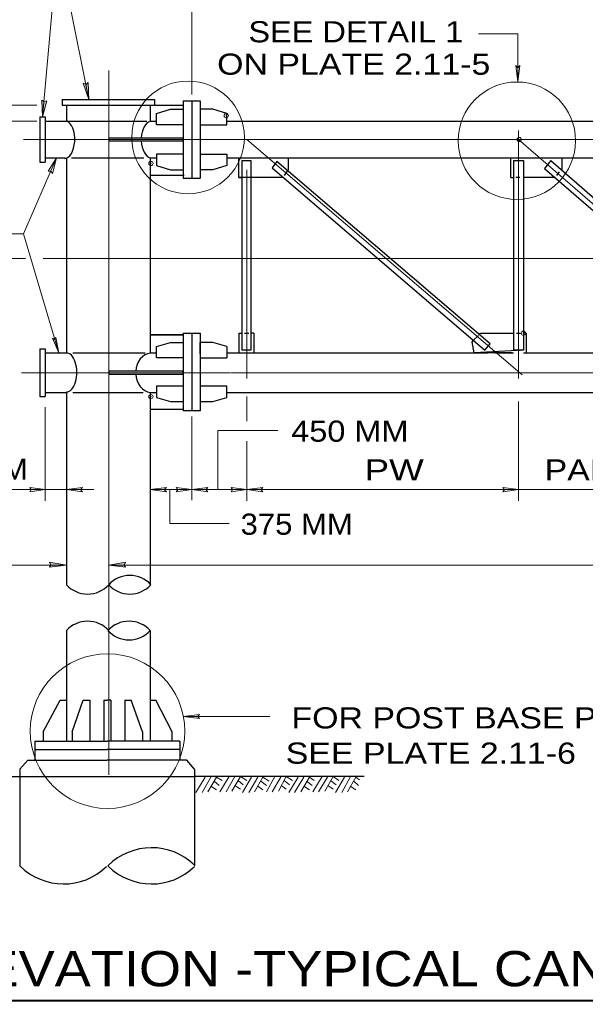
# Model space of a CAD drawing. Extents: x 312601.858 to 312602.699, y 144420.109 to 144420.704.
# Drawn here: x 312601.9927 to 312602.0731, y 144420.4937 to 144420.6329 of the extents above; entities that cross this region are included whole.
import ezdxf
from ezdxf.enums import TextEntityAlignment as Align

# ---------------------------------------------------------------- set-up
doc = ezdxf.new("R2010")
doc.units = 0
doc.header["$LTSCALE"] = 0.0012
doc.header["$PDMODE"] = 32
doc.header["$PDSIZE"] = 0.0006
for name, pattern in [('DOT_DASHED', [7.7, 5, -1.2, 0.3, -1.2]), ('LONG_DASHED', [7.5, 6, -1.5]), ('MEDIUM_DASHED', [4.5, 3, -1.5])]:
    doc.linetypes.add(name, pattern=pattern)
for name, color, linetype, lineweight in [('1', 7, 'Continuous', 13), ('2', 7, 'Continuous', 25), ('39', 7, 'Continuous', 13)]:
    doc.layers.add(name, color=color, linetype=linetype, lineweight=lineweight)

msp = doc.modelspace()

# ---------------------------------------------------------------- hatches: boundary and pattern name
at = {"layer": '39'}
for points in [[(312602.0022, 144420.6237), (312602.0025, 144420.624), (312602.0026, 144420.6216), (312602.0018, 144420.6239)], [(312601.9962, 144420.6213), (312601.9966, 144420.6214), (312601.996, 144420.6191), (312601.9959, 144420.6215)], [(312601.9972, 144420.5555), (312601.997, 144420.5559), (312601.9994, 144420.5555), (312601.997, 144420.5552)], [(312602.0076, 144420.5555), (312602.0078, 144420.5552), (312602.0054, 144420.5555), (312602.0078, 144420.5559)]]:
    msp.add_hatch(color=256, dxfattribs=at).paths.add_polyline_path(points)

# ---------------------------------------------------------------- linework, layer by layer
at = {"layer": '1'}
for p, q in [((312602.0026, 144420.6216), (312601.9982, 144420.6435)), ((312602.0172, 144420.6414), (312602.0172, 144420.6223)), ((312602.0579, 144420.6309), (312602.0635, 144420.6309)), ((312602.0635, 144420.6309), (312602.0635, 144420.6241)), ((312601.9878, 144420.6208), (312601.9952, 144420.6208)), ((312601.9879, 144420.6185), (312601.9952, 144420.6185)), ((312601.9843, 144420.6025), (312601.9933, 144420.6025)), ((312601.9818, 144420.599), (312601.9936, 144420.599)), ((312602.025, 144420.5759), (312602.025, 144420.5794)), ((312602.0636, 144420.5646), (312602.0636, 144420.5787)), ((312601.9964, 144420.5779), (312601.9964, 144420.5646)), ((312602.0172, 144420.5766), (312602.0172, 144420.5647)), ((312602.0209, 144420.5746), (312602.0294, 144420.5746)), ((312602.025, 144420.5646), (312602.025, 144420.5731)), ((312601.9994, 144420.5662), (312602.0033, 144420.5662)), ((312602.0113, 144420.5662), (312602.0168, 144420.5662)), ((312602.0168, 144420.5662), (312602.025, 144420.5662)), ((312602.025, 144420.5662), (312602.0636, 144420.5662)), ((312602.0636, 144420.5662), (312602.1312, 144420.5662)), ((312602.0141, 144420.5614), (312602.0225, 144420.5614)), ((312601.9823, 144420.5555), (312601.9994, 144420.5555)), ((312602.0054, 144420.5555), (312602.1817, 144420.5555)), ((312601.9994, 144420.5363), (312601.9987, 144420.5363)), ((312602.016, 144420.534), (312602.0283, 144420.534)), ((312602.0178, 144420.5232), (312602.0191, 144420.5254)), ((312602.0187, 144420.5232), (312602.0199, 144420.5254)), ((312602.0195, 144420.5233), (312602.0207, 144420.5254)), ((312602.0207, 144420.5254), (312602.0215, 144420.5249)), ((312602.0212, 144420.5233), (312602.0225, 144420.5255)), ((312602.0221, 144420.5233), (312602.0233, 144420.5255)), ((312602.0229, 144420.5234), (312602.0241, 144420.5255)), ((312602.0241, 144420.5255), (312602.025, 144420.5249)), ((312602.0244, 144420.5232), (312602.0257, 144420.5254)), ((312602.0253, 144420.5232), (312602.0266, 144420.5254)), ((312602.0261, 144420.5233), (312602.0273, 144420.5254)), ((312602.0273, 144420.5254), (312602.0282, 144420.5248)), ((312602.0278, 144420.5233), (312602.029, 144420.5255)), ((312602.0286, 144420.5233), (312602.0299, 144420.5255)), ((312602.0295, 144420.5234), (312602.0306, 144420.5255)), ((312602.0306, 144420.5255), (312602.0315, 144420.5249)), ((312602.031, 144420.5232), (312602.0323, 144420.5254)), ((312602.0318, 144420.5232), (312602.0331, 144420.5254)), ((312602.0327, 144420.5233), (312602.0339, 144420.5254)), ((312602.0339, 144420.5254), (312602.0346, 144420.5249)), ((312602.0344, 144420.5233), (312602.0357, 144420.5255)), ((312602.0352, 144420.5233), (312602.0365, 144420.5255)), ((312602.0361, 144420.5234), (312602.0373, 144420.5255)), ((312602.0373, 144420.5255), (312602.0381, 144420.5249)), ((312602.0376, 144420.5232), (312602.0389, 144420.5254)), ((312602.0385, 144420.5232), (312602.0397, 144420.5254)), ((312602.0393, 144420.5233), (312602.0405, 144420.5254)), ((312602.0405, 144420.5254), (312602.041, 144420.525)), ((312602.0199, 144420.5241), (312602.0207, 144420.5236)), ((312602.0204, 144420.5248), (312602.0211, 144420.5242)), ((312602.0233, 144420.5242), (312602.0241, 144420.5237)), ((312602.0238, 144420.5249), (312602.0245, 144420.5243)), ((312602.0266, 144420.5241), (312602.0273, 144420.5236)), ((312602.027, 144420.5248), (312602.0278, 144420.5242)), ((312602.0299, 144420.5242), (312602.0306, 144420.5237)), ((312602.0303, 144420.5249), (312602.0311, 144420.5243)), ((312602.0331, 144420.5241), (312602.0339, 144420.5236)), ((312602.0335, 144420.5248), (312602.0343, 144420.5242)), ((312602.0365, 144420.5242), (312602.0373, 144420.5237)), ((312602.0369, 144420.5249), (312602.0377, 144420.5243)), ((312602.0397, 144420.5241), (312602.0405, 144420.5236)), ((312602.0402, 144420.5248), (312602.0409, 144420.5242))]:
    msp.add_line(p, q, dxfattribs=at)
at = {"layer": '1', "lineweight": 25}
for p, q in [((312601.9988, 144420.6216), (312602.0119, 144420.6216)), ((312601.9988, 144420.6216), (312601.9988, 144420.6208)), ((312602.0119, 144420.6216), (312602.0119, 144420.6208)), ((312601.9988, 144420.6208), (312602.0119, 144420.6208)), ((312601.9994, 144420.6208), (312601.9994, 144420.6185)), ((312602.0113, 144420.6208), (312602.0113, 144420.6185)), ((312601.9956, 144420.6191), (312601.9956, 144420.6127)), ((312601.9956, 144420.6191), (312601.9964, 144420.6191)), ((312601.9964, 144420.6191), (312601.9964, 144420.6127)), ((312601.9964, 144420.6185), (312601.9994, 144420.6185)), ((312602.0113, 144420.6185), (312602.0122, 144420.6185)), ((312602.0222, 144420.6185), (312602.1817, 144420.6185)), ((312601.9964, 144420.6133), (312601.9992, 144420.6133)), ((312601.9994, 144420.6133), (312601.9994, 144420.5856)), ((312602.0113, 144420.6133), (312602.0122, 144420.6133)), ((312602.0113, 144420.6133), (312602.0113, 144420.5856)), ((312602.0222, 144420.6133), (312602.0255, 144420.6133)), ((312602.0239, 144420.6105), (312602.0239, 144420.6133)), ((312602.0239, 144420.6105), (312602.0239, 144420.6133)), ((312602.0239, 144420.6105), (312602.0239, 144420.6133)), ((312602.0243, 144420.6129), (312602.0243, 144420.586)), ((312602.0243, 144420.6129), (312602.0256, 144420.6129)), ((312602.0255, 144420.6133), (312602.0293, 144420.6133)), ((312602.0256, 144420.6129), (312602.0256, 144420.586)), ((312602.0293, 144420.6128), (312602.0286, 144420.6119)), ((312602.029, 144420.6133), (312602.063, 144420.6133)), ((312602.0596, 144420.5869), (312602.0293, 144420.6128)), ((312602.0629, 144420.6129), (312602.0629, 144420.586)), ((312602.0629, 144420.6129), (312602.0643, 144420.6129)), ((312602.0641, 144420.6133), (312602.0679, 144420.6133)), ((312602.0682, 144420.6129), (312602.0673, 144420.6118)), ((312602.0677, 144420.6133), (312602.1012, 144420.6133)), ((312602.0682, 144420.6129), (312602.0981, 144420.5869)), ((312602.0698, 144420.6117), (312602.0698, 144420.6133)), ((312601.9956, 144420.6127), (312601.9964, 144420.6127)), ((312602.0286, 144420.6119), (312602.0588, 144420.586)), ((312602.0673, 144420.6118), (312602.0972, 144420.5859)), ((312602.0698, 144420.6117), (312602.0697, 144420.6116)), ((312602.0239, 144420.6105), (312602.0243, 144420.6105)), ((312602.0239, 144420.6105), (312602.0243, 144420.6105)), ((312602.0239, 144420.6105), (312602.0243, 144420.6105)), ((312602.03, 144420.6105), (312602.0256, 144420.6105)), ((312602.03, 144420.6105), (312602.0256, 144420.6105)), ((312602.0625, 144420.6105), (312602.0629, 144420.6105)), ((312602.0638, 144420.6105), (312602.0632, 144420.6105)), ((312602.0694, 144420.6113), (312602.069, 144420.6108)), ((312602.0239, 144420.5884), (312602.0243, 144420.5884)), ((312602.0239, 144420.5884), (312602.0239, 144420.5856)), ((312602.0247, 144420.5884), (312602.0253, 144420.5884)), ((312602.026, 144420.5884), (312602.0256, 144420.5884)), ((312602.026, 144420.5884), (312602.026, 144420.5856)), ((312602.058, 144420.5882), (312602.0582, 144420.5884)), ((312602.0582, 144420.5884), (312602.0629, 144420.5884)), ((312602.0582, 144420.5884), (312602.0626, 144420.5884)), ((312602.0582, 144420.5884), (312602.0626, 144420.5884)), ((312602.0582, 144420.5884), (312602.0626, 144420.5884)), ((312602.0633, 144420.5884), (312602.0639, 144420.5884)), ((312602.0647, 144420.5884), (312602.0643, 144420.5884)), ((312602.0647, 144420.5884), (312602.0647, 144420.5856)), ((312602.0184, 144420.5855), (312602.0184, 144420.5871)), ((312602.0222, 144420.5865), (312602.0222, 144420.5849)), ((312602.0588, 144420.586), (312602.0596, 144420.5869)), ((312601.9956, 144420.5862), (312601.9956, 144420.5794)), ((312601.9956, 144420.5862), (312601.9964, 144420.5862)), ((312601.9964, 144420.5862), (312601.9964, 144420.5794)), ((312601.9964, 144420.5856), (312601.9994, 144420.5856)), ((312602.0113, 144420.5856), (312602.0122, 144420.5856)), ((312602.0222, 144420.5856), (312602.0226, 144420.5856)), ((312602.0223, 144420.5856), (312602.0256, 144420.5856)), ((312602.0233, 144420.5856), (312602.0234, 144420.5856)), ((312602.0256, 144420.586), (312602.0243, 144420.586)), ((312602.0256, 144420.5856), (312602.0592, 144420.5856)), ((312602.0627, 144420.5856), (312602.0589, 144420.5856)), ((312602.0603, 144420.5856), (312602.0624, 144420.5856)), ((312602.0604, 144420.5856), (312602.0627, 144420.5856)), ((312602.0606, 144420.5856), (312602.0627, 144420.5856)), ((312602.0625, 144420.5856), (312602.0606, 144420.5856)), ((312602.0608, 144420.5856), (312602.0629, 144420.5856)), ((312602.0643, 144420.586), (312602.0629, 144420.586)), ((312602.0643, 144420.5856), (312602.0976, 144420.5856)), ((312601.9956, 144420.5794), (312601.9964, 144420.5794)), ((312601.9964, 144420.58), (312601.9994, 144420.58)), ((312601.9994, 144420.58), (312601.9994, 144420.5527)), ((312602.0113, 144420.58), (312602.0113, 144420.5527)), ((312602.0113, 144420.58), (312602.0122, 144420.58)), ((312602.0222, 144420.58), (312602.0226, 144420.58)), ((312602.0222, 144420.58), (312602.1817, 144420.58)), ((312602.0233, 144420.58), (312602.0234, 144420.58)), ((312602.0184, 144420.5774), (312602.016, 144420.5774)), ((312601.9994, 144420.5462), (312601.9994, 144420.5305)), ((312602.0113, 144420.5462), (312602.0113, 144420.5305)), ((312601.9961, 144420.5318), (312601.9985, 144420.5363)), ((312601.9985, 144420.5363), (312601.9994, 144420.5363)), ((312602.0018, 144420.5363), (312602.0027, 144420.5363)), ((312602.0027, 144420.5363), (312602.0027, 144420.5305)), ((312602.0047, 144420.5363), (312602.0047, 144420.5305)), ((312602.0047, 144420.5363), (312602.0052, 144420.5363)), ((312602.0057, 144420.5363), (312602.0052, 144420.5363)), ((312602.0057, 144420.5363), (312602.0057, 144420.5305)), ((312602.0077, 144420.5363), (312602.0086, 144420.5363)), ((312602.0077, 144420.5363), (312602.0077, 144420.5305)), ((312602.0113, 144420.5363), (312602.0121, 144420.5363)), ((312602.0144, 144420.5318), (312602.0121, 144420.5363)), ((312601.9961, 144420.5318), (312601.9961, 144420.5305)), ((312602.0002, 144420.5318), (312602.0002, 144420.5305)), ((312602.0102, 144420.5318), (312602.0102, 144420.5305)), ((312602.0144, 144420.5306), (312602.0144, 144420.5318)), ((312601.9949, 144420.5305), (312602.0052, 144420.5305)), ((312601.9949, 144420.5305), (312601.9949, 144420.5279)), ((312601.9949, 144420.5293), (312602.0052, 144420.5293)), ((312602.0155, 144420.5305), (312602.0052, 144420.5305)), ((312602.0155, 144420.5293), (312602.0052, 144420.5293)), ((312602.0155, 144420.5305), (312602.0155, 144420.5279)), ((312601.9928, 144420.5265), (312601.9939, 144420.5278)), ((312601.9939, 144420.5278), (312602.0052, 144420.5278)), ((312602.0165, 144420.5278), (312602.0052, 144420.5278)), ((312602.0176, 144420.5265), (312602.0165, 144420.5278)), ((312601.9688, 144420.5255), (312602.0175, 144420.5255)), ((312602.0417, 144420.5255), (312602.0176, 144420.5255))]:
    msp.add_line(p, q, dxfattribs=at)
at = {"layer": '1', "linetype": 'MEDIUM_DASHED', "lineweight": 25}
for p, q in [((312601.9997, 144420.6185), (312602.0108, 144420.6185)), ((312602.0001, 144420.6133), (312602.0104, 144420.6133)), ((312602.0003, 144420.5856), (312602.0106, 144420.5856)), ((312602.0003, 144420.58), (312602.0103, 144420.58))]:
    msp.add_line(p, q, dxfattribs=at)
at = {"layer": '1', "linetype": 'DOT_DASHED'}
for p, q in [((312602.0636, 144420.582), (312602.0636, 144420.6172)), ((312601.9933, 144420.6159), (312602.1862, 144420.6159)), ((312602.025, 144420.6159), (312602.0641, 144420.5825)), ((312602.0636, 144420.6159), (312602.1019, 144420.5828)), ((312602.0639, 144420.6159), (312602.0637, 144420.6159)), ((312602.025, 144420.582), (312602.025, 144420.6116)), ((312601.9961, 144420.599), (312602.181, 144420.599)), ((312601.993, 144420.5828), (312602.0117, 144420.5828)), ((312602.012, 144420.5828), (312602.0226, 144420.5828)), ((312602.0222, 144420.5828), (312602.0226, 144420.5828)), ((312602.0233, 144420.5828), (312602.0234, 144420.5828))]:
    msp.add_line(p, q, dxfattribs=at)
at = {"layer": '1', "linetype": 'LONG_DASHED', "lineweight": 25}
for p, q in [((312601.9928, 144420.5265), (312601.9928, 144420.5128)), ((312602.0176, 144420.5265), (312602.0176, 144420.5128))]:
    msp.add_line(p, q, dxfattribs=at)
at = {"layer": '1', "lineweight": 40}
msp.add_line((312601.9778, 144420.4937), (312602.169, 144420.4937), dxfattribs=at)
at = {"layer": '1'}
for points in [[(312602.0638, 144420.6264), (312602.0635, 144420.6241), (312602.0632, 144420.6264), (312602.0635, 144420.6261)], [(312601.9968, 144420.6114), (312601.998, 144420.6133), (312601.9974, 144420.6111), (312601.9972, 144420.6114)], [(312601.9979, 144420.5878), (312601.9983, 144420.5856), (312601.9974, 144420.5877), (312601.9977, 144420.5875)], [(312601.9942, 144420.5665), (312601.9964, 144420.5662), (312601.9942, 144420.5659), (312601.9944, 144420.5662)], [(312602.0017, 144420.5659), (312601.9994, 144420.5662), (312602.0017, 144420.5665), (312602.0014, 144420.5662)], [(312602.0136, 144420.5659), (312602.0113, 144420.5662), (312602.0136, 144420.5665), (312602.0133, 144420.5662)], [(312602.015, 144420.5665), (312602.0172, 144420.5662), (312602.015, 144420.5659), (312602.0152, 144420.5662)], [(312602.0195, 144420.5659), (312602.0172, 144420.5662), (312602.0195, 144420.5665), (312602.0192, 144420.5662)], [(312602.0228, 144420.5665), (312602.025, 144420.5662), (312602.0228, 144420.5659), (312602.023, 144420.5662)], [(312602.0273, 144420.5659), (312602.025, 144420.5662), (312602.0273, 144420.5665), (312602.027, 144420.5662)], [(312602.0614, 144420.5665), (312602.0636, 144420.5662), (312602.0614, 144420.5659), (312602.0616, 144420.5662)], [(312602.0183, 144420.5337), (312602.016, 144420.534), (312602.0183, 144420.5343), (312602.018, 144420.534)]]:
    msp.add_lwpolyline(points, close=True, dxfattribs=at)
for points in [[(312601.9983, 144420.5856), (312601.9933, 144420.6025), (312601.998, 144420.6133)], [(312601.9778, 144420.5662), (312601.9964, 144420.5662), (312601.9994, 144420.5662)]]:
    msp.add_lwpolyline(points, dxfattribs=at)
at = {"layer": '1', "lineweight": 25}
for points in [[(312602.03, 144420.6105), (312602.0256, 144420.6105), (312602.0246, 144420.6105), (312602.0239, 144420.6105), (312602.0239, 144420.6133), (312602.0309, 144420.6133), (312602.0309, 144420.6116), (312602.0308, 144420.6115), (312602.0303, 144420.6108)], [(312602.0643, 144420.6129), (312602.0643, 144420.586), (312602.0573, 144420.5856), (312602.057, 144420.5872)], [(312602.0625, 144420.6105), (312602.0625, 144420.6133), (312602.0695, 144420.6133)], [(312602.0301, 144420.6106), (312602.03, 144420.6105), (312602.0256, 144420.6105)], [(312602.0688, 144420.6106), (312602.0687, 144420.6105), (312602.0643, 144420.6105)], [(312602.057, 144420.5872), (312602.0572, 144420.5874), (312602.0579, 144420.5881)]]:
    msp.add_lwpolyline(points, dxfattribs=at)
at = {"layer": '1', "linetype": 'DOT_DASHED'}
for points in [[(312602.0111, 144420.5828), (312602.0117, 144420.5828), (312602.0224, 144420.5828)], [(312602.0227, 144420.5828), (312602.0234, 144420.5828), (312602.1868, 144420.5828)]]:
    msp.add_lwpolyline(points, dxfattribs=at)
at = {"layer": '1'}
for centre, radius in [((312602.016675, 144420.6162), 0.0080013), ((312602.06337, 144420.61573), 0.0083339), ((312602.00523, 144420.53192), 0.0109732)]:
    msp.add_circle(centre, radius, dxfattribs=at)
for centre, start, end in [((312602.02495, 144420.61301), 180, 180.74184), ((312602.063925, 144420.61291), 180, 180.74184), ((312602.048813, 144420.595468), 49.4714, 50.21324), ((312602.048907, 144420.59535), 49.4795, 50.22134), ((312602.059478, 144420.58593), 49.1584, 49.90024), ((312602.059652, 144420.586019), 49.1584, 49.90024), ((312602.024275, 144420.58599), 0, 0.74184), ((312602.059919, 144420.585775), 49.1584, 49.90024), ((312602.062875, 144420.58609), 0, 0.74184), ((312602.063125, 144420.585895), 0, 0.74184), ((312602.06325, 144420.58589), 0, 0.74184), ((312602.063375, 144420.585895), 0, 0.74184), ((312602.063375, 144420.585895), 0, 0.74184)]:
    msp.add_arc(centre, 0.00068, start, end, dxfattribs=at)
at = {"layer": '1', "lineweight": 25}
for centre, major_axis, ratio, start_param, end_param in [((312601.99911, 144420.6159), (0, 0.0027), 0.545275, 3.1378998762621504, 6.088696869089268), ((312602.01149, 144420.6158), (0, 0.0027), 0.545275, 0.1283453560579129, 1.4614472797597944), ((312602.01149, 144420.616), (-0, -0.0027), 0.545275, 4.8217380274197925, 6.154839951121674), ((312601.99941, 144420.582835), (0, 0.002765), 0.532457, 3.1378998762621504, 6.329970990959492), ((312602.01152, 144420.582765), (-0, -0.002835), 0.809524, 3.2339238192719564, 4.630572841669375), ((312602.01152, 144420.582835), (-0, 0.002835), 0.809524, 1.6526124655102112, 3.0492614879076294)]:
    msp.add_ellipse(centre, major_axis=major_axis, ratio=ratio, start_param=start_param, end_param=end_param, dxfattribs=at)
at = {"layer": '1'}
for p in [(312602.0221, 144420.6193), (312602.0637, 144420.6159), (312602.0114, 144420.6125), (312602.0643, 144420.5884), (312602.0114, 144420.5794)]:
    msp.add_point(p, dxfattribs=at)
at = {"layer": '2', "lineweight": 13}
for p, q in [((312601.996, 144420.6191), (312601.9982, 144420.6435)), ((312602.0209, 144420.5662), (312602.0209, 144420.5746)), ((312602.0141, 144420.5662), (312602.0141, 144420.5614))]:
    msp.add_line(p, q, dxfattribs=at)
at = {"layer": '2', "linetype": 'DOT_DASHED', "lineweight": 13}
msp.add_line((312602.0054, 144420.5257), (312602.0054, 144420.6292), dxfattribs=at)
at = {"layer": '2'}
for p, q in [((312602.016, 144420.6214), (312602.0184, 144420.6214)), ((312602.016, 144420.6214), (312602.016, 144420.6104)), ((312602.0172, 144420.6214), (312602.0172, 144420.6104)), ((312602.0184, 144420.6214), (312602.0184, 144420.6104)), ((312602.0119, 144420.6208), (312602.016, 144420.6208)), ((312602.016, 144420.618), (312602.0122, 144420.618)), ((312602.0184, 144420.618), (312602.0222, 144420.618)), ((312602.016, 144420.6138), (312602.0122, 144420.6138)), ((312602.0184, 144420.6138), (312602.0222, 144420.6138)), ((312602.0161, 144420.6108), (312602.0114, 144420.6108)), ((312602.016, 144420.6104), (312602.0184, 144420.6104)), ((312602.016, 144420.5884), (312602.0184, 144420.5884)), ((312602.016, 144420.5884), (312602.016, 144420.5774)), ((312602.0172, 144420.5884), (312602.0172, 144420.5774)), ((312602.0184, 144420.5884), (312602.0184, 144420.5774)), ((312602.016, 144420.5849), (312602.0122, 144420.5849)), ((312602.0157, 144420.5849), (312602.0122, 144420.5849)), ((312602.0184, 144420.5849), (312602.0222, 144420.5849)), ((312602.0222, 144420.5809), (312602.0184, 144420.5809)), ((312602.016, 144420.5776), (312602.0113, 144420.5776)), ((312602.0002, 144420.5318), (312602.0018, 144420.5363)), ((312602.0102, 144420.5318), (312602.0086, 144420.5363))]:
    msp.add_line(p, q, dxfattribs=at)
for points in [[(312602.0122, 144420.618), (312602.0122, 144420.6196), (312602.0142, 144420.6202), (312602.016, 144420.6202)], [(312602.0222, 144420.618), (312602.0222, 144420.6196), (312602.0202, 144420.6202), (312602.0184, 144420.6202)], [(312602.0122, 144420.6138), (312602.0122, 144420.6122), (312602.0142, 144420.6116), (312602.016, 144420.6116)], [(312602.0222, 144420.6138), (312602.0222, 144420.6122), (312602.0202, 144420.6116), (312602.0184, 144420.6116)], [(312602.016, 144420.5882), (312602.0113, 144420.5882), (312602.016, 144420.5882)], [(312602.0122, 144420.5849), (312602.0122, 144420.5865), (312602.0142, 144420.5871), (312602.016, 144420.5871)], [(312602.0222, 144420.5865), (312602.0202, 144420.5871), (312602.0184, 144420.5871)], [(312602.016, 144420.5809), (312602.0122, 144420.5809), (312602.0122, 144420.5793), (312602.0142, 144420.5787), (312602.016, 144420.5787)], [(312602.0184, 144420.5787), (312602.0202, 144420.5787), (312602.0222, 144420.5793), (312602.0222, 144420.5809)]]:
    msp.add_lwpolyline(points, dxfattribs=at)
for points in [[(312602.0054, 144420.6157), (312602.016, 144420.6157), (312602.016, 144420.6161), (312602.0054, 144420.6161)], [(312602.0054, 144420.5826), (312602.016, 144420.5826), (312602.016, 144420.583), (312602.0054, 144420.583)]]:
    msp.add_lwpolyline(points, close=True, dxfattribs=at)
for centre, radius, start, end in [((312602.0084, 144420.54995), 0.0040697, 42.51045, 137.48955), ((312602.0024, 144420.55545), 0.0040697, 222.51045, 317.48955), ((312602.0084, 144420.55545), 0.0040697, 222.51045, 317.48955), ((312602.0024, 144420.54345), 0.0040697, 42.51045, 137.48955), ((312602.0083, 144420.54345), 0.0040697, 42.51045, 137.48955), ((312602.0083, 144420.54895), 0.0040697, 222.51045, 317.48955), ((312602.011501, 144420.506602), 0.008767, 45.91695, 135.01467), ((312601.999001, 144420.518998), 0.008767, 224.98533, 314.08305), ((312602.011501, 144420.518998), 0.008767, 224.98533, 314.08305)]:
    msp.add_arc(centre, radius, start, end, dxfattribs=at)
at = {"layer": '39'}
for points in [[(312602.0022, 144420.6237), (312602.0025, 144420.624), (312602.0026, 144420.6216), (312602.0018, 144420.6239)], [(312601.9962, 144420.6213), (312601.9966, 144420.6214), (312601.996, 144420.6191), (312601.9959, 144420.6215)], [(312601.9972, 144420.5555), (312601.997, 144420.5559), (312601.9994, 144420.5555), (312601.997, 144420.5552)], [(312602.0076, 144420.5555), (312602.0078, 144420.5552), (312602.0054, 144420.5555), (312602.0078, 144420.5559)]]:
    msp.add_lwpolyline(points, close=True, dxfattribs=at)

# ---------------------------------------------------------------- texts
at = {"layer": '2'}
for s, height, width, p in [('SEE DETAIL 1', 0.003, 1.15, (312602.0405, 144420.6297)), ('ON PLATE 2.11-5', 0.003, 1.2, (312602.0402, 144420.6251)), ('450 MM', 0.003, 1.15, (312602.03965, 144420.573)), ('150 MM', 0.003, 1.1, (312601.98595, 144420.5676)), ('PW  ', 0.003, 1.3, (312602.0474, 144420.5675)), ('PANEL WIDTH = 1.8 M MAX', 0.003, 1.2, (312602.0984, 144420.5675)), ('375 MM', 0.003, 1.1, (312602.0321, 144420.5598)), ('FOR POST BASE PLATE DETAILS,  ', 0.003, 1.2, (312602.07175, 144420.5323)), ('SEE PLATE 2.11-6', 0.003, 1.2, (312602.05115, 144420.5273)), ('ELEVATION -TYPICAL CANTILEVER SIGN SUPPORT', 0.005, 1.15, (312602.07335, 144420.4957))]:
    msp.add_text(s, height=height, dxfattribs=dict(at, width=width)).set_placement(p, align=Align.CENTER)

doc.saveas('drawing.dxf')
